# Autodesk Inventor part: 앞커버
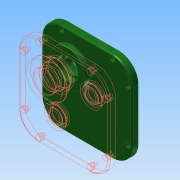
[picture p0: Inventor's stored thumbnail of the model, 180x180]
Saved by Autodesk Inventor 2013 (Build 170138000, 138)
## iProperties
Created: 2016-12
Part Number: 앞커버
Material: 알루미늄 6061
Document SubType Name: Modeling
Designer: mduedu
Density: 2.71 g/cm^3
Mass: 518.945 g
Surface Area: 476.271 cm^2
Volume: 191.493 cm^3
Author: mduedu
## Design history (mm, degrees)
sketch "스케치1"
  geometry: L1 (-46, 42)-(-46, -36); L2 (-16, 72)-(62, 72); L3 (92, 42)-(92, -36); L4 (62, -66)-(-16, -66); A1 r 30 centre (-16, -36) between (-46, -36) and (-16, -66); A2 r 30 centre (62, 42) between (92, 42) and (62, 72); A3 r 30 centre (62, -36) between (62, -66) and (92, -36); A4 r 30 centre (-16, 42) between (-16, 72) and (-46, 42); 1 further point
  constraints: 8 end point, 8 point on circle, 8 tangent, 4 centre point, 3 equal radius, 2 perpendicular, 1 horizontal
  dimensions: "d89" = 30 radius of A2; "d90" = 92 distance from line of L3 point (0, 0); "d91" = 138 distance between parallel lines of L4 L2; "d92" = 72 distance from line of point (0, 0) L2; "d114" = 46 distance from line of point (0, 0) L1
extrude "돌출1" new body sketch "스케치1" distance "d3" = 10; taper "d4" = 0 deg
sketch "스케치2"
  geometry: C1 r 21 at (0, 26); 1 further point
  constraints: 1 centre point, 1 vertical alignment
  dimensions: "d5" = 42 diameter of C1; "d7" = 26 distance of C1.centre point (0, 0)
extrude "돌출2" join sketch "스케치2" distance "d8" = 7; taper "d9" = 0 deg
sketch "스케치3"
  geometry: C1 r 15 at (0, -28.87); C2 r 21 at (0, 26) reference; C3 r 15 at (-54.87, 26); 1 further point
  constraints: 2 centre point, 1 horizontal alignment, 1 vertical alignment
  dimensions: "d10" = 30 diameter of C1; "d71" = 54.87 distance of C1.centre C2.centre; "d94" = 30 diameter of C3; "d95" = 54.87 distance of C2.centre C3.centre
extrude "돌출3" join sketch "스케치3" distance "d12" = 7; taper "d13" = 0 deg; dims "d50" = 90 deg
sketch "스케치4"
  geometry: C1 r 21 at (0, 26) reference; C2 r 28 at (0, 26); 1 further point
  constraints: 1 centre point, 1 coincident
  dimensions: "d14" = 56 diameter of C2
extrude "돌출4" join sketch "스케치4" distance "d15" = 7; taper "d16" = -5 deg
hole "구멍1" diameter "d19" = 35; stored, may be unused: countersink angle "d23" = 90 deg, drill point angle "d25" = 0 deg; dims "d17" = 10, "d18" = 10, "d20" = 6, "d21" = 4, "d22" = 2, "d24" = 10
hole "구멍2" diameter "d28" = 22; stored, may be unused: countersink angle "d32" = 90 deg, drill point angle "d34" = 0 deg; dims "d26" = 10, "d27" = 10, "d29" = 6, "d30" = 4, "d31" = 2, "d33" = 7
hole "구멍8" diameter "d98" = 22; stored, may be unused: countersink angle "d102" = 90 deg, drill point angle "d104" = 0 deg; dims "d96" = 10, "d97" = 10, "d99" = 6, "d100" = 4, "d101" = 2, "d103" = 7
hole "구멍3" diameter "d37" = 19; stored, may be unused: countersink angle "d41" = 90 deg, drill point angle "d43" = 0 deg; dims "d35" = 10, "d36" = 10, "d38" = 6, "d39" = 4, "d40" = 2, "d42" = 1
hole "구멍9" diameter "d107" = 19; stored, may be unused: countersink angle "d111" = 90 deg, drill point angle "d113" = 0 deg; dims "d105" = 10, "d106" = 10, "d108" = 6, "d109" = 4, "d110" = 2, "d112" = 1
hole "구멍4" diameter "d46" = 32; stored, may be unused: countersink angle "d50" = 90 deg, drill point angle "d52" = 0 deg; dims "d44" = 10, "d45" = 10, "d47" = 6, "d48" = 4, "d49" = 2, "d51" = 8
hole "구멍5" diameter "d55" = 25; stored, may be unused: countersink angle "d59" = 90 deg, drill point angle "d61" = 0 deg; dims "d53" = 10, "d54" = 10, "d56" = 6, "d57" = 4, "d58" = 2, "d60" = 8
fillet "모깎기1" dims "d62" = 0.3
fillet "모깎기2" dims "d63" = 2
chamfer "모따기1" distance "d64" = 1; stored, may be unused: second distance "d65" = 2, angle "d66" = 45 deg
fillet "모깎기4" dims "d68" = 2
fillet "모깎기5" dims "d69" = 0.3
fillet "모깎기6" dims "d70" = 2
sketch "스케치5"
  geometry: L1 (62, 72)-(-16, 72) reference; L2 (92, -36)-(92, 42) reference; L3 (-16, -66)-(62, -66) reference; L4 (-46, 42)-(-46, -36) reference; L5 (-40, 42)-(-40, -36); L6 (-16, -60)-(62, -60); L7 (86, -36)-(86, 42); L8 (62, 66)-(-16, 66); A1 r 30 centre (62, 42) between (92, 42) and (62, 72) reference; A2 r 30 centre (62, -36) between (62, -66) and (92, -36) reference; A3 r 30 centre (-16, -36) between (-46, -36) and (-16, -66) reference; A4 r 30 centre (-16, 42) between (-16, 72) and (-46, 42) reference; A5 r 24 centre (-16, -36) between (-40, -36) and (-16, -60); A6 r 24 centre (62, -36) between (62, -60) and (86, -36); A7 r 24 centre (62, 42) between (86, 42) and (62, 66); A8 r 24 centre (-16, 42) between (-16, 66) and (-40, 42)
  constraints: 8 end point, 8 point on circle, 4 centre point, 7 other
  dimensions: "d93" = 6 distance between parallel lines of L5 L4
sketch "스케치7"
  geometry: L1 (62, 66)-(-16, 66) reference; L2 (86, -36)-(86, 42) reference; L3 (-16, -60)-(62, -60) reference; L4 (-40, 42)-(-40, -36) reference; A1 r 24 centre (62, 42) between (86, 42) and (62, 66) reference; A2 r 24 centre (62, -36) between (62, -60) and (86, -36) reference; A3 r 24 centre (-16, -36) between (-40, -36) and (-16, -60) reference; A4 r 24 centre (-16, 42) between (-16, 66) and (-40, 42) reference; 8 further points
  constraints: 8 coincident
hole "구멍7" sketch "스케치7" at (-40, 42), (-40, -36), (-16, -60), (62, -60), (86, -36), (86, 42), (62, 66), (-16, 66) diameter "d80" = 4.5; stored, may be unused: countersink angle "d84" = 90 deg, drill point angle "d86" = 0 deg; dims "d81" = 6, "d82" = 8, "d83" = 4.6, "d85" = 8
node "솔리드1"
